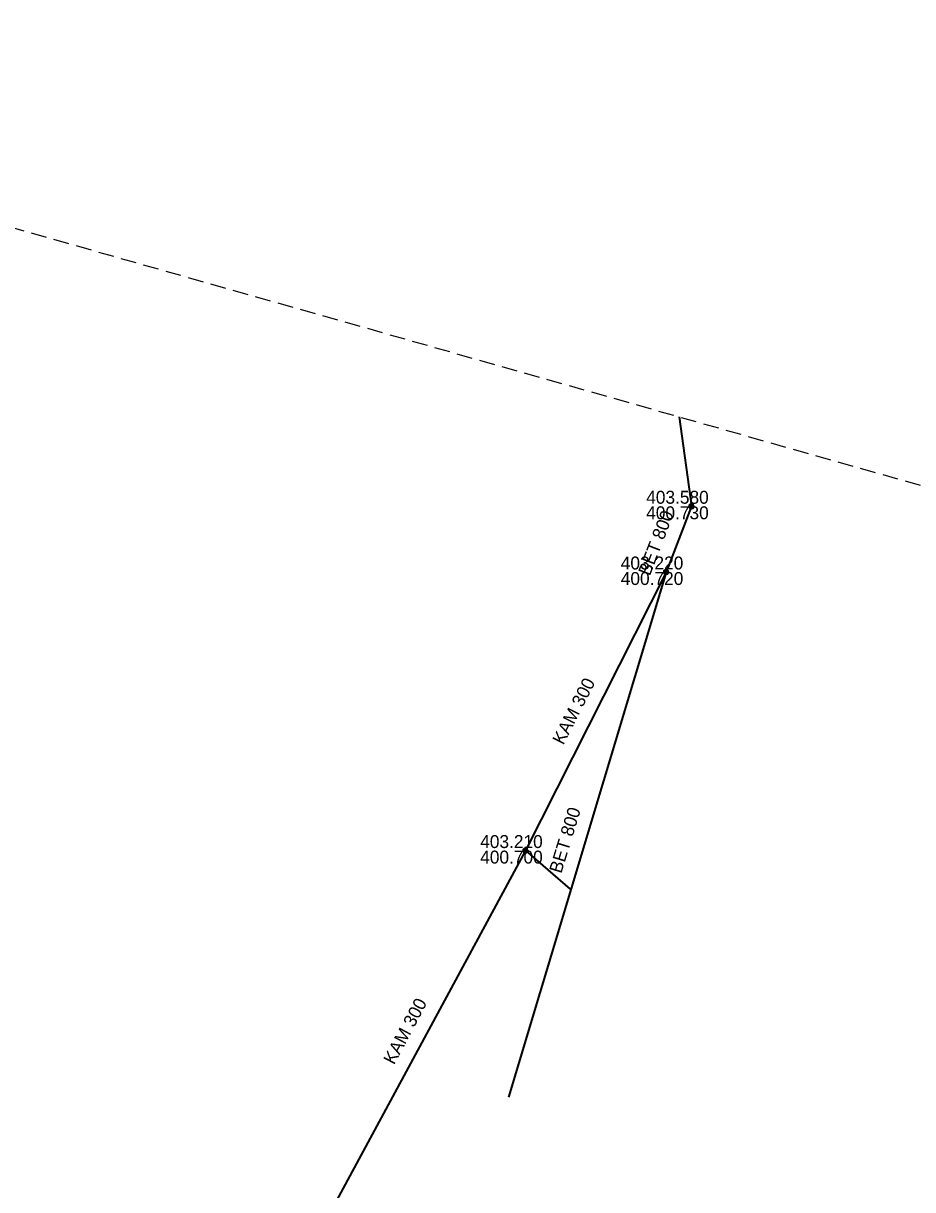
# Model space of a CAD drawing. Extents: x -873619 to -867639, y -1015082 to -1012326.
# Drawn here: x -867903.1 to -867827.5, y -1012758.3 to -1012659.1 of the extents above; entities that cross this region are included whole.
import ezdxf

# ---------------------------------------------------------------- set-up
doc = ezdxf.new("R2010")
doc.units = 0
doc.header["$LTSCALE"] = 0.44
doc.linetypes.add('MEDIUM_DASHED', pattern=[4.5, 3, -1.5])
for name, color, linetype, lineweight in [('1', 7, 'Continuous', 13), ('21', 7, 'Continuous', 35), ('30', 7, 'Continuous', 13), ('32', 7, 'Continuous', 13), ('62', 7, 'MEDIUM_DASHED', 25)]:
    doc.layers.add(name, color=color, linetype=linetype, lineweight=lineweight)

msp = doc.modelspace()

# ---------------------------------------------------------------- linework, layer by layer
at = {"layer": '21'}
for p, q in [((-867848.43, -1012705.74), (-867861.83, -1012750.4)), ((-867848.43, -1012705.74), (-867860.38, -1012729.43)), ((-867860.38, -1012729.43), (-867877.04, -1012760.3)), ((-867860.38, -1012729.43), (-867856.571, -1012732.722))]:
    msp.add_line(p, q, dxfattribs=at)
msp.add_lwpolyline([(-867847.319, -1012692.538), (-867846.27, -1012700.15), (-867848.43, -1012705.74)], dxfattribs=at)
at = {"layer": '30'}
for points in [[(-867848.199, -1012705.74), (-867848.205, -1012705.688), (-867848.222, -1012705.638), (-867848.251, -1012705.594), (-867848.288, -1012705.557), (-867848.333, -1012705.53), (-867848.383, -1012705.513), (-867848.436, -1012705.509), (-867848.488, -1012705.516), (-867848.537, -1012705.535), (-867848.58, -1012705.564), (-867848.616, -1012705.603), (-867848.642, -1012705.648), (-867848.658, -1012705.699), (-867848.661, -1012705.751), (-867848.653, -1012705.803), (-867848.633, -1012705.852), (-867848.602, -1012705.895), (-867848.563, -1012705.929), (-867848.517, -1012705.955), (-867848.466, -1012705.969), (-867848.413, -1012705.971), (-867848.362, -1012705.961), (-867848.314, -1012705.94), (-867848.271, -1012705.909), (-867848.237, -1012705.868), (-867848.213, -1012705.822), (-867848.201, -1012705.771)], [(-867848.229, -1012705.74), (-867848.235, -1012705.691), (-867848.252, -1012705.645), (-867848.28, -1012705.605), (-867848.317, -1012705.573), (-867848.361, -1012705.551), (-867848.409, -1012705.54), (-867848.458, -1012705.54), (-867848.505, -1012705.553), (-867848.548, -1012705.577), (-867848.584, -1012705.61), (-867848.611, -1012705.651), (-867848.627, -1012705.698), (-867848.631, -1012705.747), (-867848.624, -1012705.795), (-867848.605, -1012705.84), (-867848.575, -1012705.88), (-867848.537, -1012705.911), (-867848.493, -1012705.931), (-867848.445, -1012705.941), (-867848.396, -1012705.939), (-867848.349, -1012705.924), (-867848.306, -1012705.899), (-867848.272, -1012705.865), (-867848.246, -1012705.823), (-867848.232, -1012705.776)], [(-867848.259, -1012705.74), (-867848.265, -1012705.695), (-867848.282, -1012705.653), (-867848.31, -1012705.618), (-867848.346, -1012705.591), (-867848.388, -1012705.574), (-867848.433, -1012705.569), (-867848.478, -1012705.575), (-867848.519, -1012705.594), (-867848.554, -1012705.622), (-867848.581, -1012705.659), (-867848.597, -1012705.701), (-867848.601, -1012705.746), (-867848.594, -1012705.791), (-867848.575, -1012705.832), (-867848.546, -1012705.866), (-867848.509, -1012705.892), (-867848.466, -1012705.908), (-867848.421, -1012705.911), (-867848.376, -1012705.903), (-867848.336, -1012705.883), (-867848.302, -1012705.854), (-867848.276, -1012705.816), (-867848.262, -1012705.773)], [(-867848.289, -1012705.74), (-867848.294, -1012705.699), (-867848.312, -1012705.662), (-867848.339, -1012705.631), (-867848.374, -1012705.61), (-867848.414, -1012705.599), (-867848.455, -1012705.601), (-867848.494, -1012705.614), (-867848.528, -1012705.638), (-867848.553, -1012705.67), (-867848.568, -1012705.708), (-867848.571, -1012705.749), (-867848.563, -1012705.789), (-867848.543, -1012705.825), (-867848.514, -1012705.854), (-867848.477, -1012705.873), (-867848.437, -1012705.881), (-867848.396, -1012705.877), (-867848.358, -1012705.862), (-867848.326, -1012705.836), (-867848.303, -1012705.802), (-867848.29, -1012705.763)], [(-867848.319, -1012705.74), (-867848.324, -1012705.704), (-867848.342, -1012705.672), (-867848.368, -1012705.647), (-867848.402, -1012705.632), (-867848.438, -1012705.629), (-867848.473, -1012705.637), (-867848.504, -1012705.657), (-867848.527, -1012705.685), (-867848.54, -1012705.719), (-867848.54, -1012705.756), (-867848.529, -1012705.791), (-867848.508, -1012705.82), (-867848.478, -1012705.841), (-867848.443, -1012705.851), (-867848.406, -1012705.849), (-867848.372, -1012705.835), (-867848.345, -1012705.812), (-867848.326, -1012705.78), (-867848.319, -1012705.745)], [(-867848.349, -1012705.74), (-867848.354, -1012705.709), (-867848.371, -1012705.683), (-867848.397, -1012705.666), (-867848.427, -1012705.659), (-867848.458, -1012705.663), (-867848.485, -1012705.68), (-867848.503, -1012705.704), (-867848.511, -1012705.735), (-867848.507, -1012705.765), (-867848.492, -1012705.793), (-867848.468, -1012705.812), (-867848.438, -1012705.821), (-867848.407, -1012705.818), (-867848.379, -1012705.804), (-867848.359, -1012705.78), (-867848.349, -1012705.751)], [(-867848.379, -1012705.74), (-867848.384, -1012705.716), (-867848.401, -1012705.698), (-867848.424, -1012705.689), (-867848.448, -1012705.692), (-867848.469, -1012705.706), (-867848.48, -1012705.728), (-867848.48, -1012705.753), (-867848.468, -1012705.774), (-867848.448, -1012705.788), (-867848.423, -1012705.791), (-867848.4, -1012705.782), (-867848.384, -1012705.764)], [(-867848.409, -1012705.74), (-867848.414, -1012705.725), (-867848.429, -1012705.719), (-867848.444, -1012705.723), (-867848.451, -1012705.737), (-867848.447, -1012705.752), (-867848.434, -1012705.761), (-867848.419, -1012705.758), (-867848.409, -1012705.746)]]:
    msp.add_lwpolyline(points, close=True, dxfattribs=at)
at = {"layer": '32'}
for points in [[(-867846.039, -1012700.15), (-867846.045, -1012700.098), (-867846.062, -1012700.048), (-867846.091, -1012700.004), (-867846.128, -1012699.967), (-867846.173, -1012699.94), (-867846.223, -1012699.923), (-867846.276, -1012699.919), (-867846.328, -1012699.926), (-867846.377, -1012699.945), (-867846.42, -1012699.974), (-867846.456, -1012700.013), (-867846.482, -1012700.058), (-867846.498, -1012700.109), (-867846.501, -1012700.161), (-867846.493, -1012700.213), (-867846.473, -1012700.262), (-867846.442, -1012700.305), (-867846.403, -1012700.339), (-867846.357, -1012700.365), (-867846.306, -1012700.379), (-867846.253, -1012700.381), (-867846.202, -1012700.371), (-867846.154, -1012700.35), (-867846.111, -1012700.319), (-867846.077, -1012700.278), (-867846.053, -1012700.232), (-867846.041, -1012700.181)], [(-867846.069, -1012700.15), (-867846.075, -1012700.101), (-867846.092, -1012700.055), (-867846.12, -1012700.015), (-867846.157, -1012699.983), (-867846.201, -1012699.961), (-867846.249, -1012699.95), (-867846.298, -1012699.95), (-867846.345, -1012699.963), (-867846.388, -1012699.987), (-867846.424, -1012700.02), (-867846.451, -1012700.061), (-867846.467, -1012700.108), (-867846.471, -1012700.157), (-867846.464, -1012700.205), (-867846.445, -1012700.25), (-867846.415, -1012700.29), (-867846.377, -1012700.321), (-867846.333, -1012700.341), (-867846.285, -1012700.351), (-867846.236, -1012700.349), (-867846.189, -1012700.334), (-867846.146, -1012700.309), (-867846.112, -1012700.275), (-867846.086, -1012700.233), (-867846.072, -1012700.186)], [(-867846.099, -1012700.15), (-867846.105, -1012700.105), (-867846.122, -1012700.063), (-867846.15, -1012700.028), (-867846.186, -1012700.001), (-867846.228, -1012699.984), (-867846.273, -1012699.979), (-867846.318, -1012699.985), (-867846.359, -1012700.004), (-867846.394, -1012700.032), (-867846.421, -1012700.069), (-867846.437, -1012700.111), (-867846.441, -1012700.156), (-867846.434, -1012700.201), (-867846.415, -1012700.242), (-867846.386, -1012700.276), (-867846.349, -1012700.302), (-867846.306, -1012700.318), (-867846.261, -1012700.321), (-867846.216, -1012700.313), (-867846.176, -1012700.293), (-867846.142, -1012700.264), (-867846.116, -1012700.226), (-867846.102, -1012700.183)], [(-867846.129, -1012700.15), (-867846.134, -1012700.109), (-867846.152, -1012700.072), (-867846.179, -1012700.041), (-867846.214, -1012700.02), (-867846.254, -1012700.009), (-867846.295, -1012700.011), (-867846.334, -1012700.024), (-867846.368, -1012700.048), (-867846.393, -1012700.08), (-867846.408, -1012700.118), (-867846.411, -1012700.159), (-867846.403, -1012700.199), (-867846.383, -1012700.235), (-867846.354, -1012700.264), (-867846.317, -1012700.283), (-867846.277, -1012700.291), (-867846.236, -1012700.287), (-867846.198, -1012700.272), (-867846.166, -1012700.246), (-867846.143, -1012700.212), (-867846.13, -1012700.173)], [(-867846.159, -1012700.15), (-867846.164, -1012700.114), (-867846.182, -1012700.082), (-867846.208, -1012700.057), (-867846.242, -1012700.042), (-867846.278, -1012700.039), (-867846.313, -1012700.047), (-867846.344, -1012700.067), (-867846.367, -1012700.095), (-867846.38, -1012700.129), (-867846.38, -1012700.166), (-867846.369, -1012700.201), (-867846.348, -1012700.23), (-867846.318, -1012700.251), (-867846.283, -1012700.261), (-867846.246, -1012700.259), (-867846.212, -1012700.245), (-867846.185, -1012700.222), (-867846.166, -1012700.19), (-867846.159, -1012700.155)], [(-867846.189, -1012700.15), (-867846.194, -1012700.119), (-867846.211, -1012700.093), (-867846.237, -1012700.076), (-867846.267, -1012700.069), (-867846.298, -1012700.073), (-867846.325, -1012700.09), (-867846.343, -1012700.114), (-867846.351, -1012700.145), (-867846.347, -1012700.175), (-867846.332, -1012700.203), (-867846.308, -1012700.222), (-867846.278, -1012700.231), (-867846.247, -1012700.228), (-867846.219, -1012700.214), (-867846.199, -1012700.19), (-867846.189, -1012700.161)], [(-867846.219, -1012700.15), (-867846.224, -1012700.126), (-867846.241, -1012700.108), (-867846.264, -1012700.099), (-867846.288, -1012700.102), (-867846.309, -1012700.116), (-867846.32, -1012700.138), (-867846.32, -1012700.163), (-867846.308, -1012700.184), (-867846.288, -1012700.198), (-867846.263, -1012700.201), (-867846.24, -1012700.192), (-867846.224, -1012700.174)], [(-867846.249, -1012700.15), (-867846.254, -1012700.135), (-867846.269, -1012700.129), (-867846.284, -1012700.133), (-867846.291, -1012700.147), (-867846.287, -1012700.162), (-867846.274, -1012700.171), (-867846.259, -1012700.168), (-867846.249, -1012700.156)], [(-867848.199, -1012705.74), (-867848.205, -1012705.688), (-867848.222, -1012705.638), (-867848.251, -1012705.594), (-867848.288, -1012705.557), (-867848.333, -1012705.53), (-867848.383, -1012705.513), (-867848.436, -1012705.509), (-867848.488, -1012705.516), (-867848.537, -1012705.535), (-867848.58, -1012705.564), (-867848.616, -1012705.603), (-867848.642, -1012705.648), (-867848.658, -1012705.699), (-867848.661, -1012705.751), (-867848.653, -1012705.803), (-867848.633, -1012705.852), (-867848.602, -1012705.895), (-867848.563, -1012705.929), (-867848.517, -1012705.955), (-867848.466, -1012705.969), (-867848.413, -1012705.971), (-867848.362, -1012705.961), (-867848.314, -1012705.94), (-867848.271, -1012705.909), (-867848.237, -1012705.868), (-867848.213, -1012705.822), (-867848.201, -1012705.771)], [(-867848.229, -1012705.74), (-867848.235, -1012705.691), (-867848.252, -1012705.645), (-867848.28, -1012705.605), (-867848.317, -1012705.573), (-867848.361, -1012705.551), (-867848.409, -1012705.54), (-867848.458, -1012705.54), (-867848.505, -1012705.553), (-867848.548, -1012705.577), (-867848.584, -1012705.61), (-867848.611, -1012705.651), (-867848.627, -1012705.698), (-867848.631, -1012705.747), (-867848.624, -1012705.795), (-867848.605, -1012705.84), (-867848.575, -1012705.88), (-867848.537, -1012705.911), (-867848.493, -1012705.931), (-867848.445, -1012705.941), (-867848.396, -1012705.939), (-867848.349, -1012705.924), (-867848.306, -1012705.899), (-867848.272, -1012705.865), (-867848.246, -1012705.823), (-867848.232, -1012705.776)], [(-867848.259, -1012705.74), (-867848.265, -1012705.695), (-867848.282, -1012705.653), (-867848.31, -1012705.618), (-867848.346, -1012705.591), (-867848.388, -1012705.574), (-867848.433, -1012705.569), (-867848.478, -1012705.575), (-867848.519, -1012705.594), (-867848.554, -1012705.622), (-867848.581, -1012705.659), (-867848.597, -1012705.701), (-867848.601, -1012705.746), (-867848.594, -1012705.791), (-867848.575, -1012705.832), (-867848.546, -1012705.866), (-867848.509, -1012705.892), (-867848.466, -1012705.908), (-867848.421, -1012705.911), (-867848.376, -1012705.903), (-867848.336, -1012705.883), (-867848.302, -1012705.854), (-867848.276, -1012705.816), (-867848.262, -1012705.773)], [(-867848.289, -1012705.74), (-867848.294, -1012705.699), (-867848.312, -1012705.662), (-867848.339, -1012705.631), (-867848.374, -1012705.61), (-867848.414, -1012705.599), (-867848.455, -1012705.601), (-867848.494, -1012705.614), (-867848.528, -1012705.638), (-867848.553, -1012705.67), (-867848.568, -1012705.708), (-867848.571, -1012705.749), (-867848.563, -1012705.789), (-867848.543, -1012705.825), (-867848.514, -1012705.854), (-867848.477, -1012705.873), (-867848.437, -1012705.881), (-867848.396, -1012705.877), (-867848.358, -1012705.862), (-867848.326, -1012705.836), (-867848.303, -1012705.802), (-867848.29, -1012705.763)], [(-867848.319, -1012705.74), (-867848.324, -1012705.704), (-867848.342, -1012705.672), (-867848.368, -1012705.647), (-867848.402, -1012705.632), (-867848.438, -1012705.629), (-867848.473, -1012705.637), (-867848.504, -1012705.657), (-867848.527, -1012705.685), (-867848.54, -1012705.719), (-867848.54, -1012705.756), (-867848.529, -1012705.791), (-867848.508, -1012705.82), (-867848.478, -1012705.841), (-867848.443, -1012705.851), (-867848.406, -1012705.849), (-867848.372, -1012705.835), (-867848.345, -1012705.812), (-867848.326, -1012705.78), (-867848.319, -1012705.745)], [(-867848.349, -1012705.74), (-867848.354, -1012705.709), (-867848.371, -1012705.683), (-867848.397, -1012705.666), (-867848.427, -1012705.659), (-867848.458, -1012705.663), (-867848.485, -1012705.68), (-867848.503, -1012705.704), (-867848.511, -1012705.735), (-867848.507, -1012705.765), (-867848.492, -1012705.793), (-867848.468, -1012705.812), (-867848.438, -1012705.821), (-867848.407, -1012705.818), (-867848.379, -1012705.804), (-867848.359, -1012705.78), (-867848.349, -1012705.751)], [(-867848.379, -1012705.74), (-867848.384, -1012705.716), (-867848.401, -1012705.698), (-867848.424, -1012705.689), (-867848.448, -1012705.692), (-867848.469, -1012705.706), (-867848.48, -1012705.728), (-867848.48, -1012705.753), (-867848.468, -1012705.774), (-867848.448, -1012705.788), (-867848.423, -1012705.791), (-867848.4, -1012705.782), (-867848.384, -1012705.764)], [(-867848.409, -1012705.74), (-867848.414, -1012705.725), (-867848.429, -1012705.719), (-867848.444, -1012705.723), (-867848.451, -1012705.737), (-867848.447, -1012705.752), (-867848.434, -1012705.761), (-867848.419, -1012705.758), (-867848.409, -1012705.746)], [(-867860.149, -1012729.43), (-867860.155, -1012729.378), (-867860.172, -1012729.328), (-867860.201, -1012729.284), (-867860.238, -1012729.247), (-867860.283, -1012729.22), (-867860.333, -1012729.203), (-867860.386, -1012729.199), (-867860.438, -1012729.206), (-867860.487, -1012729.225), (-867860.53, -1012729.254), (-867860.566, -1012729.293), (-867860.592, -1012729.338), (-867860.608, -1012729.389), (-867860.611, -1012729.441), (-867860.603, -1012729.493), (-867860.583, -1012729.542), (-867860.552, -1012729.585), (-867860.513, -1012729.619), (-867860.467, -1012729.645), (-867860.416, -1012729.659), (-867860.363, -1012729.661), (-867860.312, -1012729.651), (-867860.264, -1012729.63), (-867860.221, -1012729.599), (-867860.187, -1012729.558), (-867860.163, -1012729.512), (-867860.151, -1012729.461)], [(-867860.179, -1012729.43), (-867860.185, -1012729.381), (-867860.202, -1012729.335), (-867860.23, -1012729.295), (-867860.267, -1012729.263), (-867860.311, -1012729.241), (-867860.359, -1012729.23), (-867860.408, -1012729.23), (-867860.455, -1012729.243), (-867860.498, -1012729.267), (-867860.534, -1012729.3), (-867860.561, -1012729.341), (-867860.577, -1012729.388), (-867860.581, -1012729.437), (-867860.574, -1012729.485), (-867860.555, -1012729.53), (-867860.525, -1012729.57), (-867860.487, -1012729.601), (-867860.443, -1012729.621), (-867860.395, -1012729.631), (-867860.346, -1012729.629), (-867860.299, -1012729.614), (-867860.256, -1012729.589), (-867860.222, -1012729.555), (-867860.196, -1012729.513), (-867860.182, -1012729.466)], [(-867860.209, -1012729.43), (-867860.215, -1012729.385), (-867860.232, -1012729.343), (-867860.26, -1012729.308), (-867860.296, -1012729.281), (-867860.338, -1012729.264), (-867860.383, -1012729.259), (-867860.428, -1012729.265), (-867860.469, -1012729.284), (-867860.504, -1012729.312), (-867860.531, -1012729.349), (-867860.547, -1012729.391), (-867860.551, -1012729.436), (-867860.544, -1012729.481), (-867860.525, -1012729.522), (-867860.496, -1012729.556), (-867860.459, -1012729.582), (-867860.416, -1012729.598), (-867860.371, -1012729.601), (-867860.326, -1012729.593), (-867860.286, -1012729.573), (-867860.252, -1012729.544), (-867860.226, -1012729.506), (-867860.212, -1012729.463)], [(-867860.239, -1012729.43), (-867860.244, -1012729.389), (-867860.262, -1012729.352), (-867860.289, -1012729.321), (-867860.324, -1012729.3), (-867860.364, -1012729.289), (-867860.405, -1012729.291), (-867860.444, -1012729.304), (-867860.478, -1012729.328), (-867860.503, -1012729.36), (-867860.518, -1012729.398), (-867860.521, -1012729.439), (-867860.513, -1012729.479), (-867860.493, -1012729.515), (-867860.464, -1012729.544), (-867860.427, -1012729.563), (-867860.387, -1012729.571), (-867860.346, -1012729.567), (-867860.308, -1012729.552), (-867860.276, -1012729.526), (-867860.253, -1012729.492), (-867860.24, -1012729.453)], [(-867860.269, -1012729.43), (-867860.274, -1012729.394), (-867860.292, -1012729.362), (-867860.318, -1012729.337), (-867860.352, -1012729.322), (-867860.388, -1012729.319), (-867860.423, -1012729.327), (-867860.454, -1012729.347), (-867860.477, -1012729.375), (-867860.49, -1012729.409), (-867860.49, -1012729.446), (-867860.479, -1012729.481), (-867860.458, -1012729.51), (-867860.428, -1012729.531), (-867860.393, -1012729.541), (-867860.356, -1012729.539), (-867860.322, -1012729.525), (-867860.295, -1012729.502), (-867860.276, -1012729.47), (-867860.269, -1012729.435)], [(-867860.299, -1012729.43), (-867860.304, -1012729.399), (-867860.321, -1012729.373), (-867860.347, -1012729.356), (-867860.377, -1012729.349), (-867860.408, -1012729.353), (-867860.435, -1012729.37), (-867860.453, -1012729.394), (-867860.461, -1012729.425), (-867860.457, -1012729.455), (-867860.442, -1012729.483), (-867860.418, -1012729.502), (-867860.388, -1012729.511), (-867860.357, -1012729.508), (-867860.329, -1012729.494), (-867860.309, -1012729.47), (-867860.299, -1012729.441)], [(-867860.329, -1012729.43), (-867860.334, -1012729.406), (-867860.351, -1012729.388), (-867860.374, -1012729.379), (-867860.398, -1012729.382), (-867860.419, -1012729.396), (-867860.43, -1012729.418), (-867860.43, -1012729.443), (-867860.418, -1012729.464), (-867860.398, -1012729.478), (-867860.373, -1012729.481), (-867860.35, -1012729.472), (-867860.334, -1012729.454)], [(-867860.359, -1012729.43), (-867860.364, -1012729.415), (-867860.379, -1012729.409), (-867860.394, -1012729.413), (-867860.401, -1012729.427), (-867860.397, -1012729.442), (-867860.384, -1012729.451), (-867860.369, -1012729.448), (-867860.359, -1012729.436)]]:
    msp.add_lwpolyline(points, close=True, dxfattribs=at)
at = {"layer": '62'}
msp.add_lwpolyline([(-873556.163, -1013770.63), (-872990.942, -1013058.87), (-872369.897, -1012591.341), (-871448.796, -1012465.737), (-870583.52, -1012702.99), (-868999.506, -1012326.176), (-868524.999, -1012528.539), (-868252.856, -1012577.385), (-867687.635, -1012737.88), (-867638.789, -1013044.914), (-867827.196, -1013184.475), (-868176.097, -1013763.652), (-868434.285, -1014335.85), (-868650.604, -1014635.906), (-869550.77, -1014963.874), (-870206.706, -1015082.5), (-871092.916, -1015026.676), (-871923.303, -1014566.126), (-872607.15, -1014370.741), (-872865.338, -1014447.499), (-873284.02, -1014259.092), (-873402.646, -1014252.114), (-873618.965, -1014280.026)], close=True, dxfattribs=at)

# ---------------------------------------------------------------- texts
at = {"layer": '1'}
for s, p in [('403.580 ', (-867850.12, -1012699.93)), ('400.730 ', (-867850.12, -1012701.25)), ('403.220 ', (-867852.28, -1012705.52)), ('400.720 ', (-867852.28, -1012706.84)), ('403.210 ', (-867864.23, -1012729.21)), ('400.700 ', (-867864.23, -1012730.53))]:
    msp.add_text(s, height=1.1, dxfattribs=at).set_placement(p)
for s, rotation, p in [('BET 800 ', 69, (-867849.809, -1012706.121)), ('KAM 300 ', 63, (-867857.164, -1012720.504)), ('BET 800 ', 73, (-867857.337, -1012731.426)), ('KAM 300 ', 62, (-867871.55, -1012747.706))]:
    msp.add_text(s, height=1.1, rotation=rotation, dxfattribs=at).set_placement(p)

doc.saveas('drawing.dxf')
